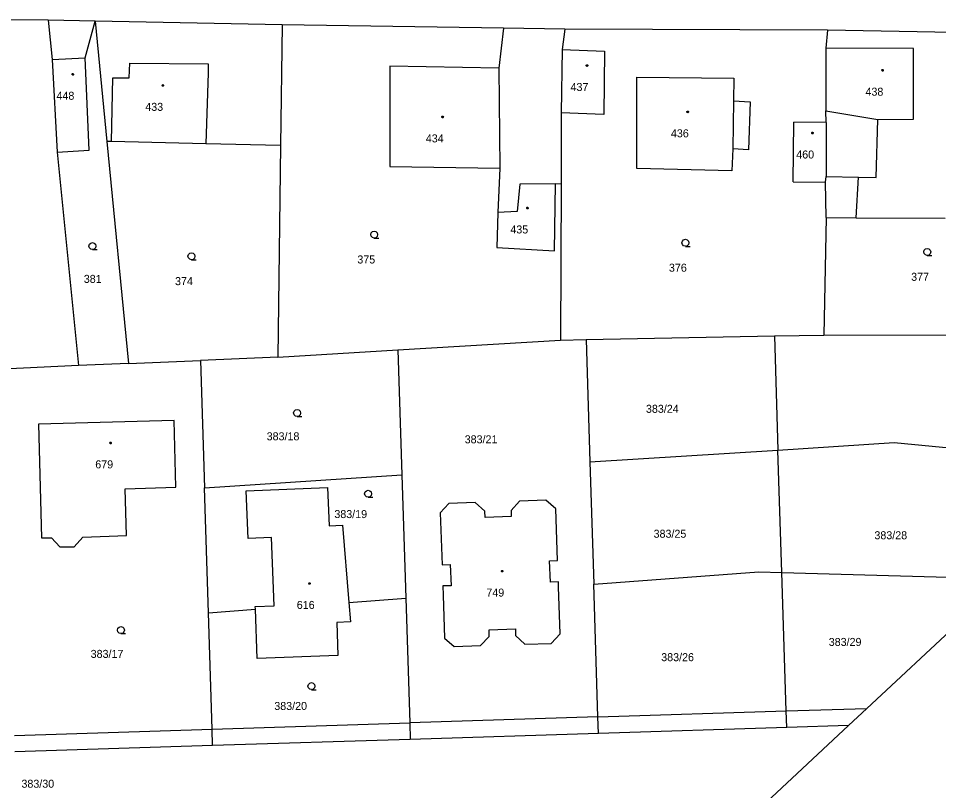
# Model space of a CAD drawing. Extents: x -757994 to -755874, y -1047691 to -1046119.
# Drawn here: x -757310.4 to -757212.7, y -1047476.6 to -1047394.6 of the extents above; entities that cross this region are included whole.
import ezdxf

# ---------------------------------------------------------------- set-up
doc = ezdxf.new("R2010")
doc.units = 0
doc.layers.add('katastrální mapa', color=7, linetype='Continuous')

msp = doc.modelspace()

# ---------------------------------------------------------------- linework, layer by layer
at = {"layer": 'katastrální mapa'}
for p, q in [((-757307.26, -1047394.79), (-757329.79, -1047394.61)), ((-757302.29, -1047394.89), (-757307.26, -1047394.79)), ((-757307.26, -1047394.79), (-757306.84, -1047398.96)), ((-757303.34, -1047398.81), (-757302.29, -1047394.89)), ((-757282.43, -1047395.31), (-757302.29, -1047394.89)), ((-757302.29, -1047394.89), (-757301.05, -1047407.67)), ((-757282.43, -1047395.31), (-757282.59, -1047408.11)), ((-757258.92, -1047395.66), (-757282.43, -1047395.31)), ((-757258.92, -1047395.66), (-757259.42, -1047399.91)), ((-757252.42, -1047395.76), (-757258.92, -1047395.66)), ((-757252.42, -1047395.76), (-757252.69, -1047397.9)), ((-757224.51, -1047395.85), (-757252.42, -1047395.76)), ((-757224.51, -1047395.85), (-757224.69, -1047397.77)), ((-757211.21, -1047396.1), (-757224.51, -1047395.85)), ((-757252.69, -1047397.9), (-757252.78, -1047404.64)), ((-757252.69, -1047397.9), (-757248.21, -1047398.1)), ((-757248.21, -1047398.1), (-757248.27, -1047404.81)), ((-757224.69, -1047397.77), (-757224.68, -1047404.42)), ((-757215.39, -1047397.8), (-757224.69, -1047397.77)), ((-757215.37, -1047405.3), (-757215.39, -1047397.8)), ((-757306.84, -1047398.96), (-757303.34, -1047398.81)), ((-757306.84, -1047398.96), (-757306.31, -1047408.83)), ((-757302.92, -1047408.59), (-757303.34, -1047398.81)), ((-757298.68, -1047400.91), (-757298.61, -1047399.35)), ((-757298.61, -1047399.35), (-757290.27, -1047399.43)), ((-757290.27, -1047399.43), (-757290.3, -1047400.4)), ((-757259.42, -1047399.91), (-757271, -1047399.7)), ((-757271, -1047399.7), (-757271, -1047410.34)), ((-757259.42, -1047399.91), (-757259.3, -1047410.5)), ((-757300.54, -1047407.68), (-757300.41, -1047400.91)), ((-757300.41, -1047400.91), (-757298.68, -1047400.91)), ((-757290.3, -1047400.4), (-757290.52, -1047407.92)), ((-757244.76, -1047400.85), (-757234.47, -1047400.95)), ((-757244.75, -1047410.55), (-757244.76, -1047400.85)), ((-757234.47, -1047400.95), (-757234.48, -1047403.35)), ((-757234.48, -1047403.35), (-757234.57, -1047408.48)), ((-757234.48, -1047403.35), (-757232.72, -1047403.48)), ((-757232.72, -1047403.48), (-757232.89, -1047408.56)), ((-757252.78, -1047404.64), (-757252.8, -1047412.16)), ((-757248.27, -1047404.81), (-757252.78, -1047404.64)), ((-757224.64, -1047405.66), (-757224.68, -1047404.42)), ((-757224.68, -1047404.42), (-757219.18, -1047405.34)), ((-757228.15, -1047411.97), (-757228.08, -1047405.62)), ((-757224.64, -1047405.66), (-757228.08, -1047405.62)), ((-757224.64, -1047405.66), (-757224.67, -1047411.39)), ((-757219.35, -1047411.51), (-757219.18, -1047405.34)), ((-757219.18, -1047405.34), (-757215.37, -1047405.3)), ((-757300.54, -1047407.68), (-757301.05, -1047407.67)), ((-757301.05, -1047407.67), (-757298.76, -1047431.27)), ((-757290.52, -1047407.92), (-757300.54, -1047407.68)), ((-757282.59, -1047408.11), (-757290.52, -1047407.92)), ((-757306.31, -1047408.83), (-757302.92, -1047408.59)), ((-757306.31, -1047408.83), (-757304.06, -1047431.49)), ((-757282.59, -1047408.11), (-757282.88, -1047430.59)), ((-757234.57, -1047408.48), (-757234.66, -1047410.8)), ((-757232.89, -1047408.56), (-757234.57, -1047408.48)), ((-757271, -1047410.34), (-757259.3, -1047410.5)), ((-757259.3, -1047410.5), (-757259.52, -1047415.22)), ((-757234.66, -1047410.8), (-757244.75, -1047410.55)), ((-757224.71, -1047412.01), (-757224.67, -1047411.39)), ((-757224.67, -1047411.39), (-757221.23, -1047411.49)), ((-757221.46, -1047415.8), (-757221.23, -1047411.49)), ((-757221.23, -1047411.49), (-757219.35, -1047411.51)), ((-757257.18, -1047412.22), (-757257.47, -1047415.13)), ((-757253.4, -1047412.17), (-757257.18, -1047412.22)), ((-757253.52, -1047419.3), (-757253.4, -1047412.17)), ((-757253.4, -1047412.17), (-757252.8, -1047412.16)), ((-757252.8, -1047412.16), (-757252.85, -1047428.78)), ((-757228.15, -1047411.97), (-757224.71, -1047412.01)), ((-757224.67, -1047415.77), (-757224.71, -1047412.01)), ((-757259.52, -1047415.22), (-757259.63, -1047418.94)), ((-757257.47, -1047415.13), (-757259.52, -1047415.22)), ((-757224.67, -1047415.77), (-757224.89, -1047428.24)), ((-757224.67, -1047415.77), (-757221.46, -1047415.8)), ((-757221.46, -1047415.8), (-757212, -1047415.82)), ((-757259.63, -1047418.94), (-757253.52, -1047419.3)), ((-757250.15, -1047428.73), (-757230.15, -1047428.34)), ((-757230.15, -1047428.34), (-757224.89, -1047428.24)), ((-757230.15, -1047428.34), (-757229.77, -1047440.45)), ((-757204.76, -1047428.29), (-757224.89, -1047428.24)), ((-757270.13, -1047429.82), (-757252.85, -1047428.78)), ((-757252.85, -1047428.78), (-757250.15, -1047428.73)), ((-757250.15, -1047428.73), (-757249.74, -1047441.71)), ((-757282.88, -1047430.59), (-757270.13, -1047429.82)), ((-757270.13, -1047429.82), (-757269.71, -1047443.09)), ((-757298.76, -1047431.27), (-757304.06, -1047431.49)), ((-757298.76, -1047431.27), (-757291.1, -1047430.94)), ((-757282.88, -1047430.59), (-757291.1, -1047430.94)), ((-757291.1, -1047430.94), (-757290.67, -1047444.47)), ((-757304.06, -1047431.49), (-757312.08, -1047431.85)), ((-757293.91, -1047437.3), (-757308.31, -1047437.7)), ((-757308.31, -1047437.7), (-757307.97, -1047449.78)), ((-757293.72, -1047444.38), (-757293.91, -1047437.3)), ((-757229.77, -1047440.45), (-757217.44, -1047439.64)), ((-757217.44, -1047439.64), (-757192.66, -1047442.08)), ((-757249.74, -1047441.71), (-757229.77, -1047440.45)), ((-757229.36, -1047453.45), (-757229.77, -1047440.45)), ((-757249.74, -1047441.71), (-757249.33, -1047454.69)), ((-757290.67, -1047444.47), (-757269.71, -1047443.09)), ((-757269.71, -1047443.09), (-757269.29, -1047456.18)), ((-757299.08, -1047444.56), (-757293.72, -1047444.38)), ((-757298.96, -1047449.52), (-757299.08, -1047444.56)), ((-757290.26, -1047457.75), (-757290.67, -1047444.47)), ((-757286.24, -1047444.79), (-757277.62, -1047444.43)), ((-757286.02, -1047449.85), (-757286.24, -1047444.79)), ((-757277.62, -1047444.43), (-757277.45, -1047448.49)), ((-757261.93, -1047446.04), (-757264.72, -1047446.14)), ((-757260.91, -1047446.96), (-757261.93, -1047446.04)), ((-757257.21, -1047445.87), (-757258.12, -1047446.86)), ((-757254.41, -1047445.77), (-757257.21, -1047445.87)), ((-757253.37, -1047446.69), (-757254.41, -1047445.77)), ((-757264.72, -1047446.14), (-757265.64, -1047447.13)), ((-757260.88, -1047447.61), (-757260.91, -1047446.96)), ((-757258.12, -1047446.86), (-757258.11, -1047447.51)), ((-757253.17, -1047452.2), (-757253.37, -1047446.69)), ((-757265.64, -1047447.13), (-757265.45, -1047452.64)), ((-757258.11, -1047447.51), (-757260.88, -1047447.61)), ((-757277.45, -1047448.49), (-757276, -1047448.42)), ((-757276, -1047448.42), (-757275.33, -1047456.63)), ((-757307.97, -1047449.78), (-757306.93, -1047449.79)), ((-757306.93, -1047449.79), (-757306.03, -1047450.74)), ((-757304.5, -1047450.73), (-757303.6, -1047449.71)), ((-757303.6, -1047449.71), (-757298.96, -1047449.52)), ((-757283.55, -1047449.75), (-757286.02, -1047449.85)), ((-757283.29, -1047456.99), (-757283.55, -1047449.75)), ((-757306.03, -1047450.74), (-757304.5, -1047450.73)), ((-757265.45, -1047452.64), (-757264.57, -1047452.61)), ((-757264.57, -1047452.61), (-757264.48, -1047454.86)), ((-757254.02, -1047452.23), (-757253.17, -1047452.2)), ((-757253.94, -1047454.49), (-757254.02, -1047452.23)), ((-757249.33, -1047454.69), (-757231.82, -1047453.38)), ((-757231.82, -1047453.38), (-757229.36, -1047453.45)), ((-757228.9, -1047468.17), (-757229.36, -1047453.45)), ((-757229.36, -1047453.45), (-757205.57, -1047454.12)), ((-757264.48, -1047454.86), (-757265.36, -1047454.89)), ((-757253.09, -1047454.46), (-757253.94, -1047454.49)), ((-757253.07, -1047454.97), (-757253.09, -1047454.46)), ((-757248.89, -1047468.8), (-757249.33, -1047454.69)), ((-757220.34, -1047467.9), (-757205.57, -1047454.12)), ((-757265.36, -1047454.89), (-757265.33, -1047455.88)), ((-757252.9, -1047459.96), (-757253.07, -1047454.97)), ((-757275.33, -1047456.63), (-757269.29, -1047456.18)), ((-757275.33, -1047456.63), (-757275.16, -1047458.69)), ((-757269.29, -1047456.18), (-757268.88, -1047469.43)), ((-757265.33, -1047455.88), (-757265.17, -1047460.43)), ((-757290.26, -1047457.75), (-757285.27, -1047457.37)), ((-757289.87, -1047470.1), (-757290.26, -1047457.75)), ((-757285.28, -1047457.06), (-757283.29, -1047456.99)), ((-757285.27, -1047457.37), (-757285.28, -1047457.06)), ((-757285.09, -1047462.59), (-757285.27, -1047457.37)), ((-757275.16, -1047458.69), (-757276.61, -1047458.77)), ((-757276.61, -1047458.77), (-757276.52, -1047462.27)), ((-757260.45, -1047459.55), (-757257.66, -1047459.44)), ((-757260.43, -1047460.25), (-757260.45, -1047459.55)), ((-757257.66, -1047459.44), (-757257.64, -1047460.14)), ((-757265.17, -1047460.43), (-757264.17, -1047461.33)), ((-757261.35, -1047461.23), (-757260.43, -1047460.25)), ((-757257.64, -1047460.14), (-757256.66, -1047461.06)), ((-757253.86, -1047461), (-757252.9, -1047459.96)), ((-757264.17, -1047461.33), (-757261.35, -1047461.23)), ((-757256.66, -1047461.06), (-757253.86, -1047461)), ((-757276.52, -1047462.27), (-757285.09, -1047462.59)), ((-757248.89, -1047468.8), (-757228.9, -1047468.17)), ((-757228.9, -1047468.17), (-757220.34, -1047467.9)), ((-757228.84, -1047469.92), (-757228.9, -1047468.17)), ((-757222.28, -1047469.72), (-757220.34, -1047467.9)), ((-757289.87, -1047470.1), (-757268.88, -1047469.43)), ((-757248.89, -1047468.8), (-757268.88, -1047469.43)), ((-757268.88, -1047469.43), (-757268.82, -1047471.18)), ((-757248.83, -1047470.55), (-757248.89, -1047468.8)), ((-757310.86, -1047470.76), (-757289.87, -1047470.1)), ((-757289.81, -1047471.84), (-757289.87, -1047470.1)), ((-757228.84, -1047469.92), (-757248.83, -1047470.55)), ((-757235.05, -1047481.62), (-757222.28, -1047469.72)), ((-757222.28, -1047469.72), (-757228.84, -1047469.92)), ((-757268.82, -1047471.18), (-757289.81, -1047471.84)), ((-757248.83, -1047470.55), (-757268.82, -1047471.18)), ((-757289.81, -1047471.84), (-757310.8, -1047472.51))]:
    msp.add_line(p, q, dxfattribs=at)
for points in [[(-757250.05, -1047399.535), (-757250, -1047399.545), (-757249.975, -1047399.59), (-757249.965, -1047399.62), (-757249.975, -1047399.665), (-757250.015, -1047399.7), (-757250.05, -1047399.705), (-757250.095, -1047399.69), (-757250.125, -1047399.66), (-757250.135, -1047399.62), (-757250.125, -1047399.575), (-757250.085, -1047399.54)], [(-757218.68, -1047400.035), (-757218.63, -1047400.045), (-757218.605, -1047400.09), (-757218.595, -1047400.12), (-757218.605, -1047400.165), (-757218.645, -1047400.2), (-757218.68, -1047400.205), (-757218.725, -1047400.19), (-757218.755, -1047400.16), (-757218.765, -1047400.12), (-757218.755, -1047400.075), (-757218.715, -1047400.04)], [(-757304.66, -1047400.465), (-757304.61, -1047400.475), (-757304.585, -1047400.52), (-757304.575, -1047400.55), (-757304.585, -1047400.595), (-757304.625, -1047400.63), (-757304.66, -1047400.635), (-757304.705, -1047400.62), (-757304.735, -1047400.59), (-757304.745, -1047400.55), (-757304.735, -1047400.505), (-757304.695, -1047400.47)], [(-757295.1, -1047401.645), (-757295.05, -1047401.655), (-757295.025, -1047401.7), (-757295.015, -1047401.73), (-757295.025, -1047401.775), (-757295.065, -1047401.81), (-757295.1, -1047401.815), (-757295.145, -1047401.8), (-757295.175, -1047401.77), (-757295.185, -1047401.73), (-757295.175, -1047401.685), (-757295.135, -1047401.65)], [(-757265.39, -1047404.995), (-757265.34, -1047405.005), (-757265.315, -1047405.05), (-757265.305, -1047405.08), (-757265.315, -1047405.125), (-757265.355, -1047405.16), (-757265.39, -1047405.165), (-757265.435, -1047405.15), (-757265.465, -1047405.12), (-757265.475, -1047405.08), (-757265.465, -1047405.035), (-757265.425, -1047405)], [(-757239.36, -1047404.455), (-757239.31, -1047404.465), (-757239.285, -1047404.51), (-757239.275, -1047404.54), (-757239.285, -1047404.585), (-757239.325, -1047404.62), (-757239.36, -1047404.625), (-757239.405, -1047404.61), (-757239.435, -1047404.58), (-757239.445, -1047404.54), (-757239.435, -1047404.495), (-757239.395, -1047404.46)], [(-757226.1, -1047406.705), (-757226.05, -1047406.715), (-757226.025, -1047406.76), (-757226.015, -1047406.79), (-757226.025, -1047406.835), (-757226.065, -1047406.87), (-757226.1, -1047406.875), (-757226.145, -1047406.86), (-757226.175, -1047406.83), (-757226.185, -1047406.79), (-757226.175, -1047406.745), (-757226.135, -1047406.71)], [(-757256.37, -1047414.665), (-757256.32, -1047414.675), (-757256.295, -1047414.72), (-757256.285, -1047414.75), (-757256.295, -1047414.795), (-757256.335, -1047414.83), (-757256.37, -1047414.835), (-757256.415, -1047414.82), (-757256.445, -1047414.79), (-757256.455, -1047414.75), (-757256.445, -1047414.705), (-757256.405, -1047414.67)], [(-757300.66, -1047439.615), (-757300.61, -1047439.625), (-757300.585, -1047439.67), (-757300.575, -1047439.7), (-757300.585, -1047439.745), (-757300.625, -1047439.78), (-757300.66, -1047439.785), (-757300.705, -1047439.77), (-757300.735, -1047439.74), (-757300.745, -1047439.7), (-757300.735, -1047439.655), (-757300.695, -1047439.62)], [(-757259.07, -1047453.235), (-757259.02, -1047453.245), (-757258.995, -1047453.29), (-757258.985, -1047453.32), (-757258.995, -1047453.365), (-757259.035, -1047453.4), (-757259.07, -1047453.405), (-757259.115, -1047453.39), (-757259.145, -1047453.36), (-757259.155, -1047453.32), (-757259.145, -1047453.275), (-757259.105, -1047453.24)], [(-757279.53, -1047454.545), (-757279.48, -1047454.555), (-757279.455, -1047454.6), (-757279.445, -1047454.63), (-757279.455, -1047454.675), (-757279.495, -1047454.71), (-757279.53, -1047454.715), (-757279.575, -1047454.7), (-757279.605, -1047454.67), (-757279.615, -1047454.63), (-757279.605, -1047454.585), (-757279.565, -1047454.55)]]:
    msp.add_lwpolyline(points, close=True, dxfattribs=at)
for points in [[(-757272.65, -1047417.94), (-757272.84, -1047417.89), (-757272.975, -1047417.755), (-757273.025, -1047417.57), (-757272.975, -1047417.385), (-757272.84, -1047417.25), (-757272.655, -1047417.2), (-757272.47, -1047417.25), (-757272.335, -1047417.385), (-757272.285, -1047417.575), (-757272.335, -1047417.765), (-757272.47, -1047417.9), (-757272.66, -1047417.95), (-757272.16, -1047417.95)], [(-757302.57, -1047419.16), (-757302.76, -1047419.11), (-757302.895, -1047418.975), (-757302.945, -1047418.79), (-757302.895, -1047418.605), (-757302.76, -1047418.47), (-757302.575, -1047418.42), (-757302.39, -1047418.47), (-757302.255, -1047418.605), (-757302.205, -1047418.795), (-757302.255, -1047418.985), (-757302.39, -1047419.12), (-757302.58, -1047419.17), (-757302.08, -1047419.17)], [(-757239.6, -1047418.81), (-757239.79, -1047418.76), (-757239.925, -1047418.625), (-757239.975, -1047418.44), (-757239.925, -1047418.255), (-757239.79, -1047418.12), (-757239.605, -1047418.07), (-757239.42, -1047418.12), (-757239.285, -1047418.255), (-757239.235, -1047418.445), (-757239.285, -1047418.635), (-757239.42, -1047418.77), (-757239.61, -1047418.82), (-757239.11, -1047418.82)], [(-757292.05, -1047420.24), (-757292.24, -1047420.19), (-757292.375, -1047420.055), (-757292.425, -1047419.87), (-757292.375, -1047419.685), (-757292.24, -1047419.55), (-757292.055, -1047419.5), (-757291.87, -1047419.55), (-757291.735, -1047419.685), (-757291.685, -1047419.875), (-757291.735, -1047420.065), (-757291.87, -1047420.2), (-757292.06, -1047420.25), (-757291.56, -1047420.25)], [(-757213.92, -1047419.78), (-757214.11, -1047419.73), (-757214.245, -1047419.595), (-757214.295, -1047419.41), (-757214.245, -1047419.225), (-757214.11, -1047419.09), (-757213.925, -1047419.04), (-757213.74, -1047419.09), (-757213.605, -1047419.225), (-757213.555, -1047419.415), (-757213.605, -1047419.605), (-757213.74, -1047419.74), (-757213.93, -1047419.79), (-757213.43, -1047419.79)], [(-757280.83, -1047436.89), (-757281.02, -1047436.84), (-757281.155, -1047436.705), (-757281.205, -1047436.52), (-757281.155, -1047436.335), (-757281.02, -1047436.2), (-757280.835, -1047436.15), (-757280.65, -1047436.2), (-757280.515, -1047436.335), (-757280.465, -1047436.525), (-757280.515, -1047436.715), (-757280.65, -1047436.85), (-757280.84, -1047436.9), (-757280.34, -1047436.9)], [(-757273.29, -1047445.46), (-757273.48, -1047445.41), (-757273.615, -1047445.275), (-757273.665, -1047445.09), (-757273.615, -1047444.905), (-757273.48, -1047444.77), (-757273.295, -1047444.72), (-757273.11, -1047444.77), (-757272.975, -1047444.905), (-757272.925, -1047445.095), (-757272.975, -1047445.285), (-757273.11, -1047445.42), (-757273.3, -1047445.47), (-757272.8, -1047445.47)], [(-757299.54, -1047459.94), (-757299.73, -1047459.89), (-757299.865, -1047459.755), (-757299.915, -1047459.57), (-757299.865, -1047459.385), (-757299.73, -1047459.25), (-757299.545, -1047459.2), (-757299.36, -1047459.25), (-757299.225, -1047459.385), (-757299.175, -1047459.575), (-757299.225, -1047459.765), (-757299.36, -1047459.9), (-757299.55, -1047459.95), (-757299.05, -1047459.95)], [(-757279.31, -1047465.9), (-757279.5, -1047465.85), (-757279.635, -1047465.715), (-757279.685, -1047465.53), (-757279.635, -1047465.345), (-757279.5, -1047465.21), (-757279.315, -1047465.16), (-757279.13, -1047465.21), (-757278.995, -1047465.345), (-757278.945, -1047465.535), (-757278.995, -1047465.725), (-757279.13, -1047465.86), (-757279.32, -1047465.91), (-757278.82, -1047465.91)]]:
    msp.add_lwpolyline(points, dxfattribs=at)

# ---------------------------------------------------------------- texts
for s, p in [('437', (-757251.801, -1047402.32)), ('438', (-757220.481, -1047402.82)), ('448', (-757306.391, -1047403.25)), ('433', (-757296.961, -1047404.43)), ('434', (-757267.171, -1047407.78)), ('436', (-757241.141, -1047407.24)), ('460', (-757227.831, -1047409.49)), ('435', (-757258.191, -1047417.45)), ('375', (-757274.441, -1047420.64)), ('376', (-757241.351, -1047421.51)), ('377', (-757215.631, -1047422.48)), ('381', (-757303.491, -1047422.7)), ('374', (-757293.801, -1047422.94)), ('383/24', (-757243.791, -1047436.5)), ('383/18', (-757284.071, -1047439.42)), ('383/21', (-757263.041, -1047439.74)), ('679', (-757302.271, -1047442.4)), ('383/19', (-757276.881, -1047447.68)), ('383/25', (-757242.981, -1047449.77)), ('383/28', (-757219.531, -1047449.93)), ('749', (-757260.741, -1047456.02)), ('616', (-757280.872, -1047457.33)), ('383/29', (-757224.381, -1047461.26)), ('383/17', (-757302.761, -1047462.53)), ('383/26', (-757242.171, -1047462.88)), ('383/20', (-757283.261, -1047468.06)), ('383/30', (-757310.111, -1047476.32))]:
    msp.add_text(s, height=0.85, dxfattribs=at).set_placement(p)

doc.saveas('drawing.dxf')
